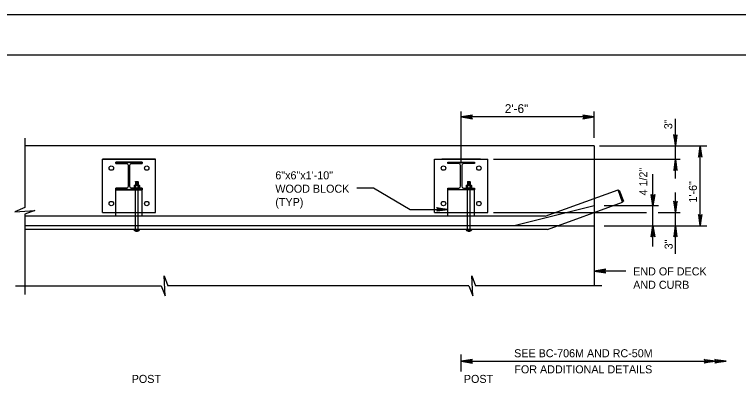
# Model space of a CAD drawing. Extents: x 641054 to 641910, y 298137 to 299325.
# Drawn here: x 641408.6 to 641679, y 299187.3 to 299325.4 of the extents above; entities that cross this region are included whole.
import ezdxf

# ---------------------------------------------------------------- set-up
doc = ezdxf.new("R2010")
doc.units = 0
for name, color, linetype in [('1', 7, 'Continuous'), ('2', 7, 'Continuous'), ('Default', 7, 'Continuous'), ('PLT-BNDY', 7, 'Continuous')]:
    doc.layers.add(name, color=color, linetype=linetype)

msp = doc.modelspace()

# ---------------------------------------------------------------- linework, layer by layer
at = {"layer": '1'}
for p, q in [((641453.42, 299261.63), (641453.29, 299261.55)), ((641453.29, 299261.55), (641453.29, 299260.69)), ((641453.42, 299261.63), (641455.14, 299261.63)), ((641453.77, 299262.92), (641453.85, 299263.01)), ((641453.77, 299262.92), (641453.77, 299261.63)), ((641453.77, 299262.92), (641454.8, 299262.92)), ((641453.77, 299262.66), (641454.8, 299262.66)), ((641453.77, 299262.4), (641454.8, 299262.4)), ((641453.77, 299262.14), (641454.8, 299262.14)), ((641453.77, 299261.89), (641454.8, 299261.89)), ((641453.77, 299261.55), (641453.77, 299260.69)), ((641453.85, 299263.01), (641454.71, 299263.01)), ((641453.85, 299262.79), (641454.72, 299262.79)), ((641453.85, 299262.53), (641454.72, 299262.53)), ((641453.85, 299262.27), (641454.72, 299262.27)), ((641453.85, 299262.02), (641454.72, 299262.02)), ((641453.85, 299261.76), (641454.72, 299261.76)), ((641454.8, 299262.92), (641454.71, 299263.01)), ((641454.8, 299262.92), (641454.8, 299261.63)), ((641454.8, 299261.55), (641454.8, 299260.69)), ((641455.14, 299261.63), (641455.28, 299261.55)), ((641455.28, 299261.55), (641455.28, 299260.69)), ((641577.44, 299261.63), (641577.3, 299261.55)), ((641577.3, 299261.55), (641577.3, 299260.69)), ((641577.44, 299261.63), (641579.16, 299261.63)), ((641577.78, 299262.92), (641577.87, 299263.01)), ((641577.78, 299262.92), (641577.78, 299261.63)), ((641577.78, 299262.92), (641578.81, 299262.92)), ((641577.78, 299262.66), (641578.81, 299262.66)), ((641577.78, 299262.4), (641578.81, 299262.4)), ((641577.78, 299262.14), (641578.81, 299262.14)), ((641577.78, 299261.89), (641578.81, 299261.89)), ((641577.78, 299261.55), (641577.78, 299260.69)), ((641577.86, 299262.79), (641578.73, 299262.79)), ((641577.86, 299262.53), (641578.73, 299262.53)), ((641577.86, 299262.27), (641578.73, 299262.27)), ((641577.86, 299262.02), (641578.73, 299262.02)), ((641577.86, 299261.76), (641578.73, 299261.76)), ((641577.87, 299263.01), (641578.73, 299263.01)), ((641578.81, 299262.92), (641578.73, 299263.01)), ((641578.81, 299262.92), (641578.81, 299261.63)), ((641578.81, 299261.55), (641578.81, 299260.69)), ((641579.16, 299261.63), (641579.29, 299261.55)), ((641579.29, 299261.55), (641579.29, 299260.69)), ((641453.42, 299260.61), (641453.29, 299260.69)), ((641455.14, 299260.61), (641453.42, 299260.61)), ((641455.14, 299260.61), (641455.28, 299260.69)), ((641577.44, 299260.61), (641577.3, 299260.69)), ((641579.16, 299260.61), (641577.44, 299260.61)), ((641579.16, 299260.61), (641579.29, 299260.69)), ((641454.85, 299245.06), (641453.72, 299245.06)), ((641578.87, 299245.06), (641577.73, 299245.06)), ((641575.41, 299195.95), (641674.32, 299195.95))]:
    msp.add_line(p, q, dxfattribs=at)
for centre, radius, start, end in [((641453.53, 299261.22), 0.409, 54.2974, 89.9999), ((641454.28, 299259.85), 1.77, 73.0653, 106.9335), ((641455.04, 299261.22), 0.409, 89.9993, 125.7017), ((641577.54, 299261.22), 0.409, 54.2974, 89.9999), ((641578.3, 299259.85), 1.77, 73.0653, 106.9335), ((641579.05, 299261.22), 0.409, 89.9993, 125.7017), ((641453.53, 299261.02), 0.409, 269.9985, 305.701), ((641454.28, 299262.39), 1.77, 253.0634, 286.9317), ((641455.04, 299261.02), 0.409, 234.2959, 269.9983), ((641577.54, 299261.02), 0.409, 269.9985, 305.701), ((641578.3, 299262.39), 1.77, 253.0634, 286.9317), ((641579.05, 299261.02), 0.409, 234.2959, 269.9983)]:
    msp.add_arc(centre, radius, start, end, dxfattribs=at)
at = {"layer": '2'}
for p, q in [((641094.49, 299310.38), (641880.49, 299310.38)), ((641542.69, 299260.73), (641556.39, 299252.64)), ((641606.82, 299250.07), (641633.96, 299259.95)), ((641606.82, 299250.07), (641633.96, 299259.95)), ((641635.66, 299255.29), (641633.96, 299259.95)), ((641635.66, 299255.29), (641633.96, 299259.95)), ((641633.96, 299259.95), (641635.66, 299255.29)), ((641634.06, 299259.7), (641634.45, 299259.84)), ((641634.45, 299259.84), (641635.97, 299255.67)), ((641607.69, 299245.11), (641635.66, 299255.29)), ((641607.69, 299245.11), (641635.66, 299255.29)), ((641635.57, 299255.53), (641635.97, 299255.67)), ((641606.82, 299250.07), (641412.45, 299250.07)), ((641607.69, 299245.11), (641412.45, 299245.11))]:
    msp.add_line(p, q, dxfattribs=at)
for points in [[(641579.38, 299287.64), (641579.23, 299287.35), (641575.41, 299287.14), (641579.38, 299287.64), (641579.58, 299287.81), (641575.41, 299287.14), (641579.23, 299286.95), (641579.37, 299286.67), (641575.41, 299287.14), (641579.58, 299286.48), (641579.37, 299286.67)], [(641621.03, 299286.64), (641621.18, 299286.93), (641625.01, 299287.14), (641621.03, 299286.64), (641620.83, 299286.47), (641625.01, 299287.14), (641621.18, 299287.33), (641621.04, 299287.61), (641625.01, 299287.14), (641620.83, 299287.8), (641621.04, 299287.61)], [(641654.9, 299280.29), (641655.19, 299280.14), (641655.4, 299276.32), (641654.9, 299280.29), (641654.73, 299280.49), (641655.4, 299276.32), (641655.59, 299280.14), (641655.87, 299280.28), (641655.4, 299276.32), (641656.06, 299280.49), (641655.87, 299280.28)], [(641665.15, 299272.34), (641664.86, 299272.49), (641664.65, 299276.32), (641665.15, 299272.34), (641665.33, 299272.14), (641664.65, 299276.32), (641664.46, 299272.5), (641664.18, 299272.36), (641664.65, 299276.32), (641663.99, 299272.14), (641664.18, 299272.36)], [(641655.9, 299267.38), (641655.61, 299267.53), (641655.4, 299271.36), (641655.9, 299267.38), (641656.07, 299267.18), (641655.4, 299271.36), (641655.21, 299267.54), (641654.93, 299267.4), (641655.4, 299271.36), (641654.74, 299267.18), (641654.93, 299267.4)], [(641647.5, 299257.97), (641647.22, 299257.82), (641647.01, 299254), (641647.5, 299257.97), (641647.68, 299258.17), (641647.01, 299254), (641646.82, 299257.82), (641646.53, 299257.96), (641647.01, 299254), (641646.34, 299258.17), (641646.53, 299257.96)], [(641566.47, 299253.13), (641566.62, 299252.84), (641570.44, 299252.64), (641566.47, 299253.13), (641566.27, 299253.3), (641570.44, 299252.64), (641566.62, 299252.44), (641566.49, 299252.15), (641570.44, 299252.64), (641566.27, 299251.96), (641566.49, 299252.15)], [(641654.9, 299255.49), (641655.19, 299255.34), (641655.4, 299251.52), (641654.9, 299255.49), (641654.73, 299255.69), (641655.4, 299251.52), (641655.59, 299255.34), (641655.87, 299255.48), (641655.4, 299251.52), (641656.06, 299255.69), (641655.87, 299255.48)], [(641664.16, 299250.53), (641664.44, 299250.38), (641664.65, 299246.56), (641664.16, 299250.53), (641663.98, 299250.73), (641664.65, 299246.56), (641664.84, 299250.38), (641665.13, 299250.52), (641664.65, 299246.56), (641665.32, 299250.73), (641665.13, 299250.52)], [(641646.51, 299242.58), (641646.79, 299242.73), (641647.01, 299246.55), (641646.51, 299242.58), (641646.33, 299242.38), (641647.01, 299246.55), (641647.19, 299242.73), (641647.48, 299242.59), (641647.01, 299246.55), (641647.67, 299242.38), (641647.48, 299242.59)], [(641655.9, 299242.58), (641655.61, 299242.73), (641655.4, 299246.55), (641655.9, 299242.58), (641656.07, 299242.38), (641655.4, 299246.55), (641655.21, 299242.73), (641654.93, 299242.59), (641655.4, 299246.55), (641654.74, 299242.38), (641654.93, 299242.59)], [(641629.16, 299230.16), (641629, 299229.86), (641625.01, 299229.64), (641629.16, 299230.16), (641629.37, 299230.34), (641625.01, 299229.64), (641629, 299229.44), (641629.15, 299229.14), (641625.01, 299229.64), (641629.37, 299228.94), (641629.15, 299229.14)], [(641579.38, 299196.45), (641579.23, 299196.16), (641575.41, 299195.95), (641579.38, 299196.45), (641579.58, 299196.62), (641575.41, 299195.95), (641579.23, 299195.76), (641579.37, 299195.47), (641575.41, 299195.95), (641579.58, 299195.28), (641579.37, 299195.47)], [(641666.34, 299196.45), (641666.49, 299196.16), (641670.32, 299195.95), (641666.34, 299196.45), (641666.14, 299196.62), (641670.32, 299195.95), (641666.49, 299195.76), (641666.35, 299195.47), (641670.32, 299195.95), (641666.14, 299195.28), (641666.35, 299195.47)], [(641670.35, 299196.45), (641670.5, 299196.16), (641674.32, 299195.95), (641670.35, 299196.45), (641670.15, 299196.62), (641674.32, 299195.95), (641670.5, 299195.76), (641670.36, 299195.47), (641674.32, 299195.95), (641670.15, 299195.28), (641670.36, 299195.47)]]:
    msp.add_lwpolyline(points, dxfattribs=at)
at = {"layer": 'Default'}
for p, q in [((641575.41, 299269.76), (641575.41, 299289.12)), ((641625.01, 299279.34), (641625.01, 299289.12)), ((641625.01, 299287.14), (641575.41, 299287.14)), ((641655.4, 299264.12), (641655.4, 299286.43)), ((641412.45, 299279.28), (641412.45, 299253.3)), ((641625.01, 299276.32), (641412.45, 299276.32)), ((641625.01, 299276.32), (641625.01, 299256.69)), ((641626.99, 299276.32), (641666.5, 299276.32)), ((641626.99, 299276.32), (641667.1, 299276.32)), ((641664.65, 299246.56), (641664.65, 299276.32)), ((641441.47, 299251.52), (641441.47, 299271.36)), ((641461.31, 299271.36), (641441.47, 299271.36)), ((641441.47, 299251.52), (641441.47, 299271.36)), ((641441.47, 299271.36), (641461.31, 299271.36)), ((641444.16, 299271.36), (641458.62, 299271.36)), ((641458.62, 299271.36), (641444.16, 299271.36)), ((641456.35, 299270.32), (641446.43, 299270.32)), ((641446.43, 299270.32), (641446.43, 299269.72)), ((641446.43, 299269.72), (641446.43, 299270.32)), ((641446.43, 299270.32), (641456.35, 299270.32)), ((641446.43, 299269.72), (641450.54, 299269.72)), ((641450.54, 299269.72), (641446.43, 299269.72)), ((641452.24, 299269.72), (641456.35, 299269.72)), ((641456.35, 299269.72), (641452.24, 299269.72)), ((641456.35, 299269.72), (641456.35, 299270.32)), ((641456.35, 299270.32), (641456.35, 299269.72)), ((641461.31, 299251.52), (641461.31, 299271.36)), ((641461.31, 299251.52), (641461.31, 299271.36)), ((641565.48, 299251.52), (641565.48, 299271.36)), ((641565.48, 299271.36), (641585.33, 299271.36)), ((641582.64, 299271.36), (641568.18, 299271.36)), ((641570.44, 299269.72), (641570.44, 299270.32)), ((641570.44, 299270.32), (641580.37, 299270.32)), ((641574.55, 299269.72), (641570.44, 299269.72)), ((641580.37, 299269.72), (641576.26, 299269.72)), ((641580.37, 299270.32), (641580.37, 299269.72)), ((641585.33, 299251.52), (641585.33, 299271.36)), ((641587.41, 299271.36), (641657.13, 299271.36)), ((641451.18, 299269.08), (641451.18, 299261.25)), ((641451.18, 299261.25), (641451.18, 299269.08)), ((641451.61, 299261.25), (641451.61, 299269.08)), ((641451.61, 299269.08), (641451.61, 299261.25)), ((641575.19, 299261.25), (641575.19, 299269.08)), ((641575.62, 299269.08), (641575.62, 299261.25)), ((641647.01, 299238.85), (641647.01, 299265.84)), ((641453.77, 299245.11), (641453.77, 299261.63)), ((641454.8, 299245.11), (641454.8, 299261.63)), ((641577.78, 299245.11), (641577.78, 299261.63)), ((641578.81, 299245.11), (641578.81, 299261.63)), ((641450.54, 299260.61), (641446.43, 299260.61)), ((641446.43, 299260.61), (641446.43, 299259.99)), ((641446.43, 299259.99), (641446.43, 299260.61)), ((641446.43, 299260.61), (641450.54, 299260.61)), ((641446.43, 299259.99), (641456.35, 299259.99)), ((641446.43, 299251.52), (641446.43, 299259.99)), ((641456.35, 299259.99), (641446.43, 299259.99)), ((641446.43, 299251.52), (641446.43, 299259.99)), ((641456.35, 299260.61), (641452.24, 299260.61)), ((641452.24, 299260.61), (641456.35, 299260.61)), ((641456.35, 299259.99), (641456.35, 299260.61)), ((641456.35, 299260.61), (641456.35, 299259.99)), ((641456.35, 299251.52), (641456.35, 299259.99)), ((641456.35, 299251.52), (641456.35, 299259.99)), ((641536.47, 299260.73), (641542.69, 299260.73)), ((641570.44, 299259.99), (641570.44, 299260.61)), ((641570.44, 299260.61), (641574.55, 299260.61)), ((641580.37, 299259.99), (641570.44, 299259.99)), ((641570.44, 299251.52), (641570.44, 299259.99)), ((641576.26, 299260.61), (641580.37, 299260.61)), ((641580.37, 299260.61), (641580.37, 299259.99)), ((641580.37, 299251.52), (641580.37, 299259.99)), ((641655.4, 299236.01), (641655.4, 299258.96)), ((641625.01, 299256.69), (641625.01, 299251.41)), ((641625.01, 299254), (641595.25, 299246.56)), ((641649.02, 299254), (641628.78, 299254)), ((641412.45, 299250.82), (641412.45, 299220.84)), ((641441.47, 299251.52), (641446.43, 299251.52)), ((641446.43, 299250.07), (641446.43, 299251.52)), ((641446.43, 299250.07), (641446.43, 299251.52)), ((641446.43, 299251.52), (641456.35, 299251.52)), ((641456.35, 299250.07), (641456.35, 299251.52)), ((641456.35, 299250.07), (641456.35, 299251.52)), ((641456.35, 299251.52), (641461.31, 299251.52)), ((641556.39, 299252.64), (641570.44, 299252.64)), ((641565.48, 299251.52), (641570.44, 299251.52)), ((641570.44, 299250.07), (641570.44, 299251.52)), ((641570.44, 299251.52), (641580.37, 299251.52)), ((641580.37, 299250.07), (641580.37, 299251.52)), ((641580.37, 299251.52), (641585.33, 299251.52)), ((641587.41, 299251.52), (641644.61, 299251.52)), ((641625.01, 299251.41), (641625.01, 299224.08)), ((641649, 299251.52), (641657.13, 299251.52)), ((641611.67, 299246.56), (641412.45, 299246.56)), ((641611.67, 299246.56), (641625.01, 299246.56)), ((641628.78, 299246.56), (641667.1, 299246.56)), ((641453.22, 299245.06), (641453.78, 299245.06)), ((641453.22, 299245.05), (641453.22, 299245.06)), ((641453.22, 299245.05), (641453.78, 299245.05)), ((641453.78, 299245.05), (641453.78, 299245.06)), ((641454.79, 299245.06), (641453.78, 299245.06)), ((641454.79, 299245.06), (641454.79, 299245.05)), ((641454.79, 299245.06), (641455.34, 299245.06)), ((641454.79, 299245.05), (641455.34, 299245.05)), ((641577.24, 299245.06), (641577.79, 299245.06)), ((641577.24, 299245.05), (641577.24, 299245.06)), ((641577.24, 299245.05), (641577.79, 299245.05)), ((641577.79, 299245.05), (641577.79, 299245.06)), ((641578.81, 299245.06), (641577.79, 299245.06)), ((641578.81, 299245.06), (641578.81, 299245.05)), ((641578.81, 299245.06), (641579.36, 299245.06)), ((641578.81, 299245.05), (641579.36, 299245.05)), ((641636.82, 299229.64), (641625.01, 299229.64)), ((641409.02, 299224.08), (641463.41, 299224.08)), ((641578.26, 299224.08), (641465.89, 299224.08)), ((641627.92, 299224.08), (641580.74, 299224.08)), ((641575.41, 299192.19), (641575.41, 299198.49))]:
    msp.add_line(p, q, dxfattribs=at)
for points in [[(641412.45, 299253.3), (641408.73, 299251.79), (641416.17, 299252.24), (641412.45, 299250.82)], [(641463.41, 299224.08), (641464.92, 299220.36), (641464.47, 299227.8), (641465.89, 299224.08)], [(641578.26, 299224.08), (641579.77, 299220.36), (641579.32, 299227.8), (641580.74, 299224.08)]]:
    msp.add_lwpolyline(points, dxfattribs=at)
for centre in [(641444.78, 299268.05), (641444.78, 299268.05), (641458, 299268.05), (641458, 299268.05), (641568.79, 299268.05), (641582.02, 299268.05), (641444.78, 299254.82), (641444.78, 299254.82), (641458, 299254.82), (641458, 299254.82), (641568.79, 299254.82), (641582.02, 299254.82)]:
    msp.add_circle(centre, 0.827, dxfattribs=at)
for centre, radius, start, end in [((641450.54, 299269.08), 0.636, 0, 90), ((641450.54, 299269.08), 0.636, 0, 90), ((641452.24, 299269.08), 0.636, 90, 180), ((641452.24, 299269.08), 0.636, 90, 180), ((641574.55, 299269.08), 0.636, 0, 90), ((641576.26, 299269.08), 0.636, 90, 180), ((641450.54, 299261.25), 0.636, 270, 0), ((641450.54, 299261.25), 0.636, 270, 0), ((641452.24, 299261.25), 0.636, 180, 270), ((641452.24, 299261.25), 0.636, 180, 270), ((641574.55, 299261.25), 0.636, 270, 0), ((641576.26, 299261.25), 0.636, 180, 270), ((641454.28, 299245.83), 1.32, 216.3703, 323.6297), ((641453.72, 299245.11), 0.0512, 269.9973, 357.2783), ((641454.28, 299245.83), 0.931, 236.9318, 303.0682), ((641454.85, 299245.11), 0.0512, 182.7217, 270.0027), ((641578.3, 299245.83), 1.32, 216.3703, 323.6297), ((641577.73, 299245.11), 0.0512, 269.9973, 357.2783), ((641578.3, 299245.83), 0.931, 236.9318, 303.0682), ((641578.87, 299245.11), 0.0512, 182.7217, 270.0027)]:
    msp.add_arc(centre, radius, start, end, dxfattribs=at)
for points, degree in [([(641453.8, 299245.06), (641453.8, 299245.06), (641453.77, 299245.07), (641453.77, 299245.1), (641453.77, 299245.11), (641453.77, 299245.11)], 3), ([(641453.77, 299245.11), (641453.77, 299245.11)], 1), ([(641454.8, 299245.11), (641454.8, 299245.11), (641454.8, 299245.1), (641454.79, 299245.07), (641454.77, 299245.06), (641454.76, 299245.06)], 3), ([(641454.8, 299245.11), (641454.8, 299245.11)], 1), ([(641455.34, 299245.06), (641455.34, 299245.05)], 1), ([(641577.82, 299245.06), (641577.81, 299245.06), (641577.79, 299245.07), (641577.78, 299245.1), (641577.78, 299245.11), (641577.78, 299245.11)], 3), ([(641577.78, 299245.11), (641577.78, 299245.11)], 1), ([(641578.81, 299245.11), (641578.81, 299245.11), (641578.81, 299245.1), (641578.81, 299245.07), (641578.79, 299245.06), (641578.78, 299245.06)], 3), ([(641578.81, 299245.11), (641578.81, 299245.11)], 1), ([(641579.36, 299245.06), (641579.36, 299245.05)], 1)]:
    msp.add_open_spline(points, degree=degree, dxfattribs=at)
at = {"layer": 'PLT-BNDY'}
msp.add_lwpolyline([(641054.49, 299325.38), (641895.49, 299325.38), (641895.49, 298731.38), (641054.49, 298731.38)], close=True, dxfattribs=at)

# ---------------------------------------------------------------- texts
at = {"layer": '2'}
for s, height, p in [('2\'-6"', 3.3, (641591.68, 299288.6)), ('6"x6"x1\'-10"', 3, (641506.02, 299263.86)), ('WOOD BLOCK', 3, (641506.02, 299258.86)), ('(TYP)', 3, (641506.02, 299253.86)), ('END OF DECK', 3, (641639.63, 299228)), ('AND CURB', 3, (641639.63, 299223)), ('SEE BC-706M AND RC-50M', 3.0001, (641595.18, 299197.45)), ('FOR ADDITIONAL DETAILS', 3.0001, (641595.26, 299191.45)), ('  POST', 3, (641450.17, 299187.87)), ('  POST', 3, (641574.18, 299187.87))]:
    msp.add_text(s, height=height, dxfattribs=at).set_placement(p)
for s, p in [('3"', (641654.22, 299282.58)), ('4 1/2"', (641644.9, 299257.84)), ('1\'-6"', (641663.43, 299255.19)), ('3"', (641654.35, 299237.73))]:
    msp.add_text(s, height=3, rotation=90, dxfattribs=at).set_placement(p)

doc.saveas('drawing.dxf')
